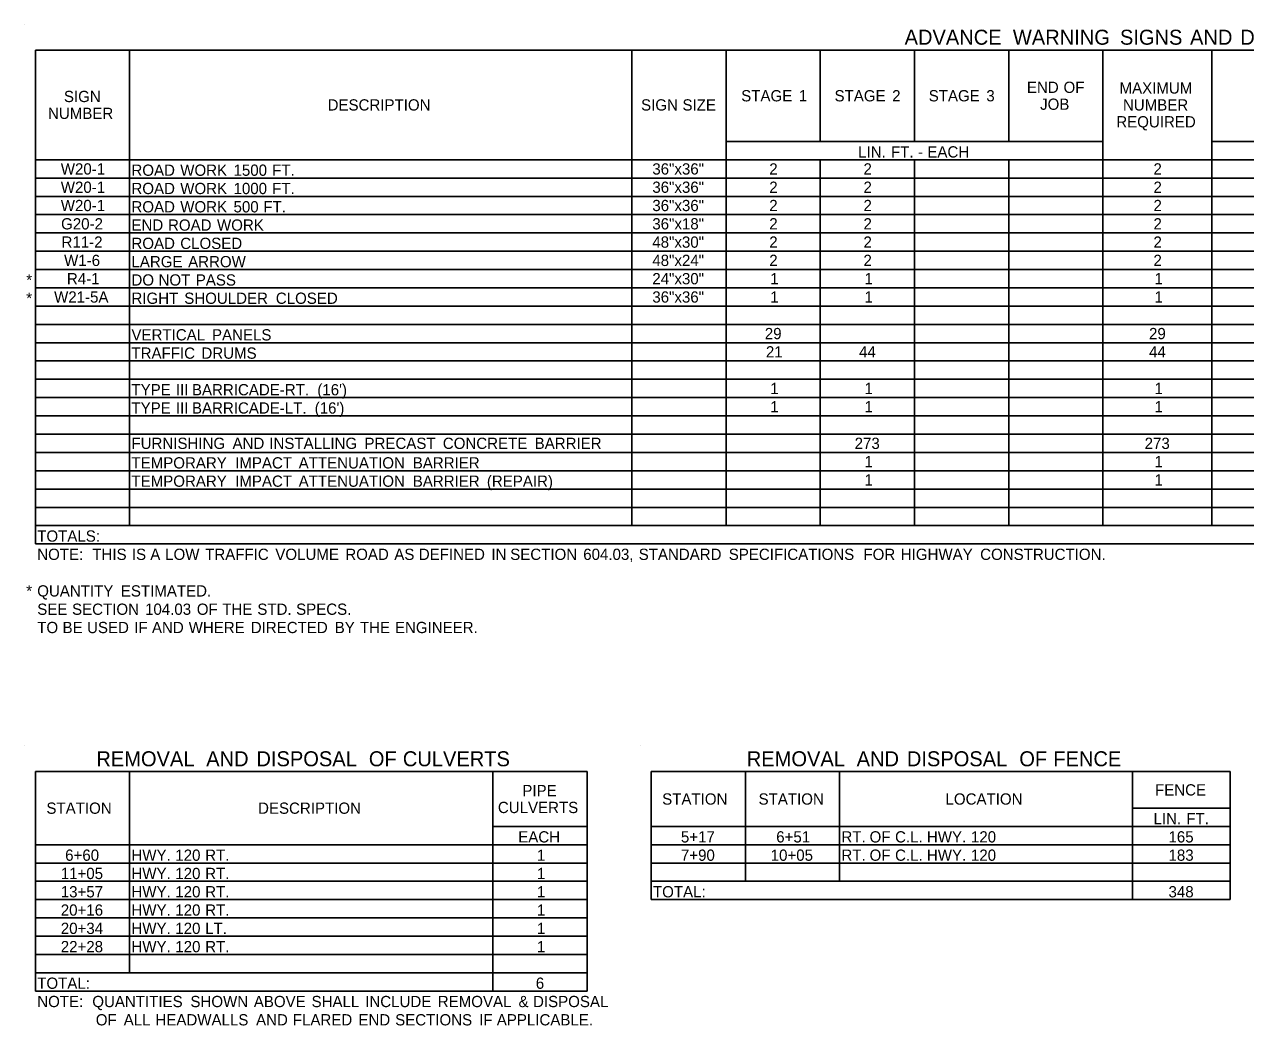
# Model space of a CAD drawing. Extents: x 1940653 to 1945779, y 534266 to 535271.
# Drawn here: x 1940653 to 1941239, y 534791 to 535271 of the extents above; entities that cross this region are included whole.
import ezdxf

# ---------------------------------------------------------------- set-up
doc = ezdxf.new("R2010")
doc.units = 0
doc.layers.add('Default', color=7, linetype='Continuous')
doc.layers.add('R_Logo', color=7, linetype='Continuous')

msp = doc.modelspace()

# ---------------------------------------------------------------- linework, layer by layer
at = {"layer": 'Default'}
for p, q in [((1940658.64, 535258.6), (1941697.16, 535258.6)), ((1940658.64, 535021.67), (1940658.64, 535258.6)), ((1940658.64, 535021.67), (1940658.64, 535258.6)), ((1940703.83, 535030.45), (1940703.83, 535258.6)), ((1940944.71, 535030.45), (1940944.71, 535258.6)), ((1940989.9, 535030.45), (1940989.9, 535258.6)), ((1941035.09, 535214.72), (1941035.09, 535258.6)), ((1941080.28, 535214.72), (1941080.28, 535258.6)), ((1941125.47, 535214.72), (1941125.47, 535258.6)), ((1941170.66, 535030.45), (1941170.66, 535258.6)), ((1941222.87, 535030.45), (1941222.87, 535258.6)), ((1940989.9, 535214.72), (1941170.66, 535214.72)), ((1941222.87, 535214.72), (1941697.16, 535214.72)), ((1940658.64, 535205.95), (1941222.87, 535205.95)), ((1940703.83, 535074.32), (1940703.83, 535205.95)), ((1940944.71, 535030.45), (1940944.71, 535205.95)), ((1940989.9, 535030.45), (1940989.9, 535205.95)), ((1941035.09, 535030.45), (1941035.09, 535205.95)), ((1941035.09, 535030.45), (1941035.09, 535205.95)), ((1941080.28, 535030.45), (1941080.28, 535205.95)), ((1941080.28, 535030.45), (1941080.28, 535205.95)), ((1941125.47, 535030.45), (1941125.47, 535205.95)), ((1941125.47, 535030.45), (1941125.47, 535205.95)), ((1941170.66, 535205.95), (1941697.16, 535205.95)), ((1941170.66, 535030.45), (1941170.66, 535205.95)), ((1940658.64, 535197.17), (1941697.16, 535197.17)), ((1940658.64, 535188.4), (1941697.16, 535188.4)), ((1940658.64, 535179.62), (1941697.16, 535179.62)), ((1940658.64, 535170.85), (1941697.16, 535170.85)), ((1940658.64, 535162.07), (1941697.16, 535162.07)), ((1940658.64, 535153.3), (1941697.16, 535153.3)), ((1940658.64, 535144.52), (1941697.16, 535144.52)), ((1940658.64, 535135.75), (1941697.16, 535135.75)), ((1940658.64, 535126.97), (1941697.16, 535126.97)), ((1940658.64, 535118.2), (1941697.16, 535118.2)), ((1940658.64, 535109.42), (1941697.16, 535109.42)), ((1940658.64, 535100.65), (1941697.16, 535100.65)), ((1940658.64, 535091.87), (1941697.16, 535091.87)), ((1940658.64, 535083.1), (1941697.16, 535083.1)), ((1940658.64, 535074.32), (1941697.16, 535074.32)), ((1940658.64, 535065.55), (1941697.16, 535065.55)), ((1940703.83, 535030.45), (1940703.83, 535065.55)), ((1940658.64, 535056.77), (1941697.16, 535056.77)), ((1940658.64, 535048), (1941697.16, 535048)), ((1940658.64, 535039.22), (1941697.16, 535039.22)), ((1940658.64, 535030.45), (1941697.16, 535030.45)), ((1940658.64, 535021.67), (1941697.16, 535021.67)), ((1940658.64, 534912.46), (1940923.21, 534912.46)), ((1940658.64, 534807.16), (1940658.64, 534912.46)), ((1940658.64, 534807.16), (1940658.64, 534912.46)), ((1940703.83, 534815.93), (1940703.83, 534912.46)), ((1940878.02, 534807.16), (1940878.02, 534912.46)), ((1940923.21, 534807.16), (1940923.21, 534912.46)), ((1940953.95, 534912.46), (1941231.68, 534912.46)), ((1940953.95, 534851.03), (1940953.95, 534912.46)), ((1940953.95, 534851.03), (1940953.95, 534912.46)), ((1940999.14, 534859.81), (1940999.14, 534912.46)), ((1941044.34, 534859.81), (1941044.34, 534912.46)), ((1941184.74, 534851.03), (1941184.74, 534912.46)), ((1941231.68, 534851.03), (1941231.68, 534912.46)), ((1941184.74, 534894.91), (1941231.68, 534894.91)), ((1940878.02, 534886.13), (1940923.21, 534886.13)), ((1940953.95, 534886.13), (1941231.68, 534886.13)), ((1940999.14, 534859.81), (1940999.14, 534886.13)), ((1941044.34, 534859.81), (1941044.34, 534886.13)), ((1941184.74, 534851.03), (1941184.74, 534886.13)), ((1940658.64, 534877.36), (1940923.21, 534877.36)), ((1940703.83, 534815.93), (1940703.83, 534877.36)), ((1940878.02, 534807.16), (1940878.02, 534877.36)), ((1940953.95, 534877.36), (1941231.68, 534877.36)), ((1940658.64, 534868.58), (1940923.21, 534868.58)), ((1940953.95, 534868.58), (1941231.68, 534868.58)), ((1940658.64, 534859.81), (1940923.21, 534859.81)), ((1940953.95, 534859.81), (1941231.68, 534859.81)), ((1940658.64, 534851.03), (1940923.21, 534851.03)), ((1940953.95, 534851.03), (1941231.68, 534851.03)), ((1940658.64, 534842.26), (1940923.21, 534842.26)), ((1940658.64, 534833.48), (1940923.21, 534833.48)), ((1940658.64, 534824.71), (1940923.21, 534824.71)), ((1940658.64, 534815.93), (1940923.21, 534815.93)), ((1940658.64, 534807.16), (1940923.21, 534807.16))]:
    msp.add_line(p, q, dxfattribs=at)
at = {"layer": 'R_Logo'}
for p, q in [((1940653.38, 535270.88), (1940653.38, 535270.88)), ((1940653.38, 534924.74), (1940653.38, 534924.74)), ((1940948.69, 534924.74), (1940948.69, 534924.74))]:
    msp.add_line(p, q, dxfattribs=at)

# ---------------------------------------------------------------- texts
at = {"layer": 'Default'}
for s, height, p in [('ADVANCE', 7.2, (1941075.51, 535261.14)), (' WARNING', 7.2, (1941124.76, 535261.14)), (' SIGNS', 7.2, (1941176.12, 535261.14)), (' AND', 7.2, (1941209.73, 535261.14)), (' DEVICES', 7.2, (1941233.82, 535261.14)), ('SIGN', 5.4, (1940672.32, 535233.62)), ('STAGE', 5.4, (1940997.15, 535233.96)), (' 1', 5.4, (1941022.77, 535233.96)), ('STAGE', 5.4, (1941041.92, 535233.96)), (' 2', 5.4, (1941067.54, 535233.96)), ('STAGE', 5.4, (1941087.08, 535233.96)), (' 3', 5.4, (1941112.7, 535233.96)), ('END', 5.4, (1941134.18, 535238.01)), (' OF', 5.4, (1941149.73, 535238.01)), ('MAXIMUM', 5.4, (1941178.6, 535237.67)), ('DESCRIPTION', 5.4, (1940798.79, 535229.57)), ('SIGN', 5.4, (1940949.13, 535229.57)), (' SIZE', 5.4, (1940966.98, 535229.57)), ('JOB', 5.4, (1941140.5, 535229.91)), ('NUMBER', 5.4, (1941180.23, 535229.57)), ('NUMBER', 5.4, (1940664.7, 535225.52)), ('REQUIRED', 5.4, (1941177.04, 535221.47)), ('LIN.', 5.4, (1941053.25, 535207.03)), (' FT.', 5.4, (1941066.98, 535207.03)), (' -', 5.4, (1941079.87, 535207.03)), (' EACH', 5.4, (1941084.42, 535207.03)), ('W20-1', 5.4, (1940670.82, 535198.86)), ('ROAD', 5.4, (1940704.71, 535198.25)), (' WORK', 5.4, (1940726.11, 535198.25)), (' 1500', 5.4, (1940751.66, 535198.25)), (' FT.', 5.4, (1940770.17, 535198.25)), ('36"x36"', 5.4, (1940954.52, 535198.86)), ('2', 5.4, (1941010.6, 535198.86)), ('2', 5.4, (1941055.79, 535198.86)), ('2', 5.4, (1941194.87, 535198.86)), ('W20-1', 5.4, (1940670.82, 535190.08)), ('ROAD', 5.4, (1940704.71, 535189.48)), (' WORK', 5.4, (1940726.11, 535189.48)), (' 1000', 5.4, (1940751.66, 535189.48)), (' FT.', 5.4, (1940770.17, 535189.48)), ('36"x36"', 5.4, (1940954.52, 535190.08)), ('2', 5.4, (1941010.6, 535190.08)), ('2', 5.4, (1941055.79, 535190.08)), ('2', 5.4, (1941194.87, 535190.08)), ('W20-1', 5.4, (1940670.82, 535181.31)), ('ROAD', 5.4, (1940704.71, 535180.7)), (' WORK', 5.4, (1940726.11, 535180.7)), (' 500', 5.4, (1940751.66, 535180.7)), (' FT.', 5.4, (1940765.97, 535180.7)), ('36"x36"', 5.4, (1940954.52, 535181.31)), ('2', 5.4, (1941010.6, 535181.31)), ('2', 5.4, (1941055.79, 535181.31)), ('2', 5.4, (1941194.87, 535181.31)), ('G20-2', 5.4, (1940670.96, 535172.53)), ('END', 5.4, (1940704.71, 535171.93)), (' ROAD', 5.4, (1940720.24, 535171.93)), (' WORK', 5.4, (1940743.73, 535171.93)), ('36"x18"', 5.4, (1940954.52, 535172.53)), ('2', 5.4, (1941010.6, 535172.53)), ('2', 5.4, (1941055.79, 535172.53)), ('2', 5.4, (1941194.87, 535172.53)), ('R11-2', 5.4, (1940671.17, 535163.76)), ('ROAD', 5.4, (1940704.71, 535163.15)), (' CLOSED', 5.4, (1940726.11, 535163.15)), ('48"x30"', 5.4, (1940954.52, 535163.76)), ('2', 5.4, (1941010.6, 535163.76)), ('2', 5.4, (1941055.79, 535163.76)), ('2', 5.4, (1941194.87, 535163.76)), ('W1-6', 5.4, (1940672.4, 535154.98)), ('LARGE', 5.4, (1940704.71, 535154.38)), (' ARROW', 5.4, (1940729.89, 535154.38)), ('48"x24"', 5.4, (1940954.52, 535154.98)), ('2', 5.4, (1941010.6, 535154.98)), ('2', 5.4, (1941055.79, 535154.98)), ('2', 5.4, (1941194.87, 535154.98)), ('*', 5.4, (1940654.25, 535145.6)), ('R4-1', 5.4, (1940673.76, 535146.21)), ('DO', 5.4, (1940704.71, 535145.6)), (' NOT', 5.4, (1940715.69, 535145.6)), (' PASS', 5.4, (1940733.56, 535145.6)), ('24"x30"', 5.4, (1940954.52, 535146.21)), ('1', 5.4, (1941011.09, 535146.21)), ('1', 5.4, (1941056.28, 535146.21)), ('1', 5.4, (1941195.36, 535146.21)), ('*', 5.4, (1940654.25, 535136.83)), ('W21-5A', 5.4, (1940667.61, 535137.43)), ('RIGHT', 5.4, (1940704.71, 535136.83)), (' SHOULDER', 5.4, (1940728.03, 535136.83)), (' CLOSED', 5.4, (1940771.95, 535136.83)), ('36"x36"', 5.4, (1940954.52, 535137.43)), ('1', 5.4, (1941011.09, 535137.43)), ('1', 5.4, (1941056.28, 535137.43)), ('1', 5.4, (1941195.36, 535137.43)), ('VERTICAL', 5.4, (1940704.71, 535119.28)), (' PANELS', 5.4, (1940741.34, 535119.28)), ('29', 5.4, (1941008.47, 535119.88)), ('29', 5.4, (1941192.74, 535119.88)), ('TRAFFIC', 5.4, (1940704.71, 535110.5)), (' DRUMS', 5.4, (1940736.27, 535110.5)), ('21', 5.4, (1941008.99, 535111.11)), ('44', 5.4, (1941053.67, 535111.11)), ('44', 5.4, (1941192.76, 535111.11)), ('TYPE', 5.4, (1940704.71, 535092.95)), (' III', 5.4, (1940724.02, 535092.95)), (' BARRICADE-RT.', 5.4, (1940731.72, 535092.95)), (" (16')", 5.4, (1940791.85, 535092.95)), ('1', 5.4, (1941011.09, 535093.56)), ('1', 5.4, (1941056.28, 535093.56)), ('1', 5.4, (1941195.36, 535093.56)), ('TYPE', 5.4, (1940704.71, 535084.18)), (' III', 5.4, (1940724.02, 535084.18)), (' BARRICADE-LT.', 5.4, (1940731.72, 535084.18)), (" (16')", 5.4, (1940790.6, 535084.18)), ('1', 5.4, (1941011.09, 535084.78)), ('1', 5.4, (1941056.28, 535084.78)), ('1', 5.4, (1941195.36, 535084.78)), ('FURNISHING', 5.4, (1940704.71, 535067.23)), (' AND', 5.4, (1940751.19, 535067.23)), (' INSTALLING', 5.4, (1940768.81, 535067.23)), (' PRECAST', 5.4, (1940814.46, 535067.23)), (' CONCRETE', 5.4, (1940852.04, 535067.23)), (' BARRIER', 5.4, (1940896.08, 535067.23)), ('273', 5.4, (1941051.56, 535067.23)), ('273', 5.4, (1941190.65, 535067.23)), ('TEMPORARY', 5.4, (1940704.71, 535057.85)), (' IMPACT', 5.4, (1940752.45, 535057.85)), (' ATTENUATION', 5.4, (1940782.9, 535057.85)), (' BARRIER', 5.4, (1940837.62, 535057.85)), ('1', 5.4, (1941056.28, 535058.46)), ('1', 5.4, (1941195.36, 535058.46)), ('TEMPORARY', 5.4, (1940704.71, 535049.08)), (' IMPACT', 5.4, (1940752.45, 535049.08)), (' ATTENUATION', 5.4, (1940782.9, 535049.08)), (' BARRIER', 5.4, (1940837.62, 535049.08)), (' (REPAIR)', 5.4, (1940873.16, 535049.08)), ('1', 5.4, (1941056.28, 535049.68)), ('1', 5.4, (1941195.36, 535049.68)), ('TOTALS:', 5.4, (1940659.52, 535022.75)), ('NOTE:', 5.4, (1940659.52, 535013.98)), ('  THIS', 5.4, (1940681.92, 535013.98)), (' IS', 5.4, (1940702.9, 535013.98)), (' A', 5.4, (1940711.73, 535013.98)), (' LOW', 5.4, (1940718.87, 535013.98)), (' TRAFFIC', 5.4, (1940738.06, 535013.98)), (' VOLUME', 5.4, (1940771.71, 535013.98)), (' ROAD', 5.4, (1940805.27, 535013.98)), (' AS', 5.4, (1940828.76, 535013.98)), (' DEFINED', 5.4, (1940840.53, 535013.98)), (' IN', 5.4, (1940875.34, 535013.98)), (' SECTION', 5.4, (1940884.36, 535013.98)), (' 604.03,', 5.4, (1940919.38, 535013.98)), (' STANDARD', 5.4, (1940945.97, 535013.98)), (' SPECIFICATIONS', 5.4, (1940989.17, 535013.98)), (' FOR', 5.4, (1941053.76, 535013.98)), (' HIGHWAY', 5.4, (1941071.68, 535013.98)), (' CONSTRUCTION.', 5.4, (1941109.76, 535013.98)), ('*', 5.4, (1940654.25, 534996.43)), ('QUANTITY', 5.4, (1940659.52, 534996.43)), (' ESTIMATED.', 5.4, (1940697.61, 534996.43)), ('SEE', 5.4, (1940659.52, 534987.65)), (' SECTION', 5.4, (1940674.22, 534987.65)), (' 104.03', 5.4, (1940709.23, 534987.65)), (' OF', 5.4, (1940734.05, 534987.65)), (' THE', 5.4, (1940746.28, 534987.65)), (' STD.', 5.4, (1940763.07, 534987.65)), (' SPECS.', 5.4, (1940781.69, 534987.65)), ('TO', 5.4, (1940659.52, 534978.88)), (' BE', 5.4, (1940669.66, 534978.88)), (' USED', 5.4, (1940681.42, 534978.88)), (' IF', 5.4, (1940704.08, 534978.88)), (' AND', 5.4, (1940712.53, 534978.88)), (' WHERE', 5.4, (1940730.16, 534978.88)), (' DIRECTED', 5.4, (1940759.93, 534978.88)), (' BY', 5.4, (1940800.19, 534978.88)), (' THE', 5.4, (1940812.3, 534978.88)), (' ENGINEER.', 5.4, (1940829.08, 534978.88)), ('REMOVAL', 7.2, (1940687.87, 534915)), (' AND', 7.2, (1940737.88, 534915)), (' DISPOSAL', 7.2, (1940761.97, 534915)), (' OF', 7.2, (1940815.89, 534915)), (' CULVERTS', 7.2, (1940832.19, 534915)), ('REMOVAL', 7.2, (1940999.83, 534915)), (' AND', 7.2, (1941049.83, 534915)), (' DISPOSAL', 7.2, (1941073.92, 534915)), (' OF', 7.2, (1941127.85, 534915)), (' FENCE', 7.2, (1941144.15, 534915)), ('PIPE', 5.4, (1940892.2, 534900.65)), ('FENCE', 5.4, (1941195.61, 534900.98)), ('STATION', 5.4, (1940959.25, 534896.6)), ('STATION', 5.4, (1941005.48, 534896.6)), ('LOCATION', 5.4, (1941095.14, 534896.6)), ('STATION', 5.4, (1940663.93, 534892.21)), ('DESCRIPTION', 5.4, (1940765.44, 534892.21)), ('CULVERTS', 5.4, (1940880.46, 534892.55)), ('LIN.', 5.4, (1941194.9, 534887.21)), (' FT.', 5.4, (1941208.63, 534887.21)), ('EACH', 5.4, (1940890.21, 534878.44)), ('5+17', 5.4, (1940968.23, 534878.44)), ('6+51', 5.4, (1941013.94, 534878.44)), ('RT.', 5.4, (1941045.21, 534878.44)), (' OF', 5.4, (1941056.71, 534878.44)), (' C.L.', 5.4, (1941068.94, 534878.44)), (' HWY.', 5.4, (1941084.21, 534878.44)), (' 120', 5.4, (1941105.34, 534878.44)), ('165', 5.4, (1941202.07, 534878.44)), ('6+60', 5.4, (1940672.93, 534869.66)), ('HWY.', 5.4, (1940704.71, 534869.66)), (' 120', 5.4, (1940723.75, 534869.66)), (' RT.', 5.4, (1940738.07, 534869.66)), ('1', 5.4, (1940899.21, 534869.66)), ('7+90', 5.4, (1940968.24, 534869.66)), ('10+05', 5.4, (1941011.3, 534869.66)), ('RT.', 5.4, (1941045.21, 534869.66)), (' OF', 5.4, (1941056.71, 534869.66)), (' C.L.', 5.4, (1941068.94, 534869.66)), (' HWY.', 5.4, (1941084.21, 534869.66)), (' 120', 5.4, (1941105.34, 534869.66)), ('183', 5.4, (1941202.09, 534869.66)), ('11+05', 5.4, (1940670.8, 534860.89)), ('HWY.', 5.4, (1940704.71, 534860.89)), (' 120', 5.4, (1940723.75, 534860.89)), (' RT.', 5.4, (1940738.07, 534860.89)), ('1', 5.4, (1940899.21, 534860.89)), ('13+57', 5.4, (1940670.82, 534852.11)), ('HWY.', 5.4, (1940704.71, 534852.11)), (' 120', 5.4, (1940723.75, 534852.11)), (' RT.', 5.4, (1940738.07, 534852.11)), ('1', 5.4, (1940899.21, 534852.11)), ('TOTAL:', 5.4, (1940954.83, 534852.11)), ('348', 5.4, (1941202.09, 534852.11)), ('20+16', 5.4, (1940670.82, 534843.34)), ('HWY.', 5.4, (1940704.71, 534843.34)), (' 120', 5.4, (1940723.75, 534843.34)), (' RT.', 5.4, (1940738.07, 534843.34)), ('1', 5.4, (1940899.21, 534843.34)), ('20+34', 5.4, (1940670.83, 534834.56)), ('HWY.', 5.4, (1940704.71, 534834.56)), (' 120', 5.4, (1940723.75, 534834.56)), (' LT.', 5.4, (1940738.07, 534834.56)), ('1', 5.4, (1940899.21, 534834.56)), ('22+28', 5.4, (1940670.81, 534825.79)), ('HWY.', 5.4, (1940704.71, 534825.79)), (' 120', 5.4, (1940723.75, 534825.79)), (' RT.', 5.4, (1940738.07, 534825.79)), ('1', 5.4, (1940899.21, 534825.79)), ('TOTAL:', 5.4, (1940659.52, 534808.24)), ('6', 5.4, (1940898.65, 534808.24)), ('NOTE:', 5.4, (1940659.52, 534799.46)), ('  QUANTITIES', 5.4, (1940681.92, 534799.46)), (' SHOWN', 5.4, (1940730.99, 534799.46)), (' ABOVE', 5.4, (1940761.39, 534799.46)), (' SHALL', 5.4, (1940789.09, 534799.46)), (' INCLUDE', 5.4, (1940814.82, 534799.46)), (' REMOVAL', 5.4, (1940849.63, 534799.46)), (' &', 5.4, (1940888.36, 534799.46)), (' DISPOSAL', 5.4, (1940895.31, 534799.46)), ('              OF', 5.4, (1940659.52, 534790.69)), (' ALL', 5.4, (1940698.98, 534790.69)), (' HEADWALLS', 5.4, (1940714.23, 534790.69)), (' AND', 5.4, (1940762.47, 534790.69)), (' FLARED', 5.4, (1940780.1, 534790.69)), (' END', 5.4, (1940811.56, 534790.69)), (' SECTIONS', 5.4, (1940829.18, 534790.69)), (' IF', 5.4, (1940869.46, 534790.69)), (' APPLICABLE.', 5.4, (1940877.91, 534790.69))]:
    msp.add_text(s, height=height, dxfattribs=at).set_placement(p)

doc.saveas('drawing.dxf')
